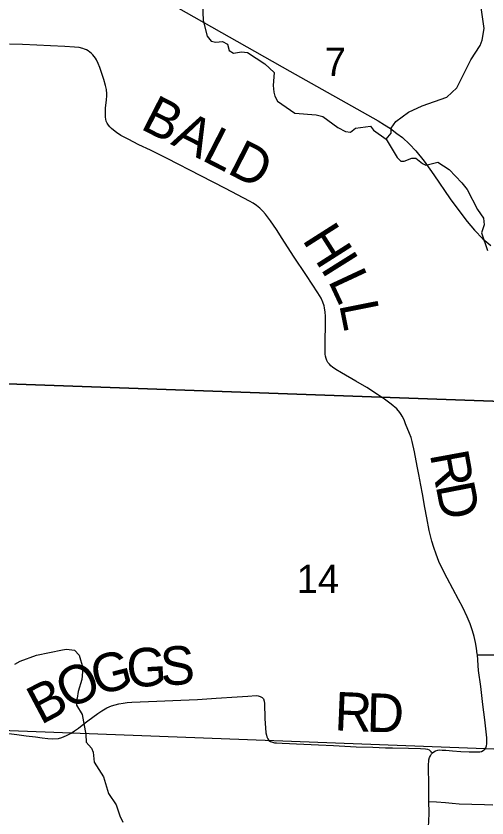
# Model space of a CAD drawing. Extents: x 0 to 34, y 0 to 22.
# Drawn here: x 6.614 to 7.308, y 17.641 to 18.823 of the extents above; entities that cross this region are included whole.
import ezdxf

# ---------------------------------------------------------------- set-up
doc = ezdxf.new("R2010")
doc.units = 0
for name, color, linetype in [('GM_X_County_Road', 7, 'Continuous'), ('GM_X_County_Road_Text', 7, 'Continuous'), ('GM_X_Minor_River', 7, 'Continuous'), ('GM_X_Rail_Line', 7, 'Continuous'), ('GM_X_Section', 7, 'Continuous'), ('GM_X_Section_Text', 7, 'Continuous'), ('GM_X_Township_Road', 7, 'Continuous'), ('GM_X_Township_Road_Text', 7, 'Continuous')]:
    doc.layers.add(name, color=color, linetype=linetype)

msp = doc.modelspace()

# ---------------------------------------------------------------- linework, layer by layer
at = {"layer": 'GM_X_County_Road'}
for points in [[(7.294, 17.8814), (7.2939, 17.8824), (7.2926, 17.8914), (7.2913, 17.8998), (7.2895, 17.9083), (7.2869, 17.917), (7.2834, 17.9272), (7.2792, 17.9373), (7.2724, 17.9511), (7.2663, 17.9631), (7.2579, 17.9787), (7.2493, 17.9945), (7.2435, 18.0058), (7.2374, 18.0189), (7.2331, 18.0298), (7.2297, 18.0395), (7.227, 18.0489), (7.2231, 18.0646), (7.2194, 18.0832), (7.2167, 18.0985), (7.213, 18.1188), (7.2105, 18.1317), (7.2078, 18.1474), (7.2055, 18.1596), (7.2013, 18.1809), (7.1979, 18.196), (7.1963, 18.2019), (7.1942, 18.2077), (7.1883, 18.2221), (7.186, 18.2278), (7.1833, 18.2332), (7.1817, 18.236), (7.1795, 18.239), (7.1754, 18.244), (7.167, 18.2511), (7.1571, 18.2584), (7.1469, 18.2654), (7.1311, 18.2754), (7.1151, 18.2849), (7.0936, 18.2973), (7.0856, 18.3021), (7.0804, 18.3057), (7.078, 18.3078), (7.0758, 18.3101), (7.0738, 18.3127), (7.0723, 18.3155), (7.0711, 18.3185), (7.0703, 18.3216), (7.0698, 18.3248), (7.0695, 18.3311), (7.0698, 18.3467), (7.0703, 18.3653), (7.0701, 18.3808), (7.0697, 18.3869), (7.0688, 18.393), (7.0682, 18.396), (7.0663, 18.4017), (7.0636, 18.4072), (7.0589, 18.4151), (7.0419, 18.441), (7.0232, 18.4695), (7.0065, 18.4956), (6.998, 18.5086), (6.9891, 18.5213), (6.9817, 18.5312), (6.9777, 18.5358), (6.9733, 18.5401), (6.9685, 18.5439), (6.9635, 18.5474), (6.9582, 18.5506), (6.9225, 18.5692), (6.8866, 18.5877), (6.8368, 18.6131), (6.812, 18.6256), (6.795, 18.6337), (6.7791, 18.6417), (6.7685, 18.6474), (6.7623, 18.6518), (6.7574, 18.6552), (6.7546, 18.6577), (6.7522, 18.66), (6.7503, 18.6623), (6.7485, 18.6654), (6.747, 18.6684), (6.7463, 18.6713), (6.7459, 18.6745), (6.7458, 18.6779), (6.7457, 18.6811), (6.746, 18.6874), (6.7474, 18.6997), (6.7478, 18.7059), (6.7477, 18.7089), (6.7471, 18.715), (6.7459, 18.721), (6.7432, 18.7298), (6.7373, 18.7474), (6.7351, 18.7532), (6.7325, 18.7587), (6.731, 18.7614), (6.7292, 18.7638), (6.7273, 18.7662), (6.7252, 18.7683), (6.7229, 18.7703), (6.7204, 18.7719), (6.7178, 18.7734), (6.7151, 18.7747), (6.7122, 18.7757), (6.7068, 18.777), (6.7004, 18.7777), (6.6859, 18.7786), (6.665, 18.7796), (6.6444, 18.7807), (6.6234, 18.7813), (6.6041, 18.7817)], [(7.2277, 17.7367), (7.2297, 17.7384), (7.2324, 17.7398), (7.2355, 17.7407), (7.2388, 17.7411), (7.242, 17.741), (7.2475, 17.7407), (7.2574, 17.7399), (7.2697, 17.739), (7.2821, 17.7386), (7.2945, 17.7382), (7.2974, 17.7383), (7.3003, 17.739), (7.3028, 17.7403), (7.305, 17.7421), (7.3066, 17.7444), (7.3076, 17.7471), (7.308, 17.7501), (7.3081, 17.7531), (7.3079, 17.7592), (7.3048, 17.7856), (7.3023, 17.8084), (7.2989, 17.8346), (7.2959, 17.8581), (7.294, 17.8814)], [(7.294, 17.8814), (7.3009, 17.8813), (7.3112, 17.8813), (7.3288, 17.8815), (7.3473, 17.8816), (7.3787, 17.8813), (7.4373, 17.8815), (7.456, 17.8815), (7.4621, 17.8811)], [(7.2227, 17.665), (7.2225, 17.6881), (7.2223, 17.698), (7.222, 17.7079), (7.2221, 17.7175), (7.2221, 17.7207), (7.2224, 17.7238), (7.2227, 17.7267), (7.2236, 17.7298), (7.2249, 17.7327), (7.2265, 17.7352), (7.2277, 17.7367)], [(7.1802, 17.3223), (7.1867, 17.3472), (7.1894, 17.3588), (7.1931, 17.3749), (7.1963, 17.3887), (7.1986, 17.3984), (7.2008, 17.4077), (7.2036, 17.4197), (7.206, 17.4299), (7.2083, 17.4409), (7.2096, 17.4482), (7.2111, 17.4564), (7.2119, 17.4638), (7.2134, 17.4847), (7.2144, 17.5034), (7.2154, 17.5259), (7.2173, 17.5649), (7.2198, 17.5933), (7.2216, 17.6233), (7.2223, 17.6353), (7.2228, 17.6488), (7.2227, 17.665)]]:
    msp.add_lwpolyline(points, dxfattribs=at)
at = {"layer": 'GM_X_Minor_River'}
for points in [[(7.1596, 18.6419), (7.1668, 18.6506), (7.1667, 18.6582), (7.1739, 18.6681), (7.1923, 18.6815), (7.2127, 18.6911), (7.249, 18.7038), (7.2637, 18.7176), (7.2846, 18.7587), (7.2982, 18.78), (7.3011, 18.7876), (7.3041, 18.8051), (7.2994, 18.8362), (7.2979, 18.8415), (7.297, 18.859), (7.3097, 18.8947)], [(6.8889, 18.8416), (6.8898, 18.8169), (6.8956, 18.7938), (6.9017, 18.7863), (6.9085, 18.7848), (6.9183, 18.786), (6.9259, 18.7818), (6.9279, 18.7727), (6.9343, 18.7686), (6.9464, 18.7705), (6.9551, 18.7695), (6.9809, 18.7529), (6.9946, 18.7404), (6.9932, 18.7211), (6.994, 18.7112), (6.9955, 18.7051), (6.9993, 18.698), (7.0248, 18.6802), (7.0562, 18.6778), (7.066, 18.6755), (7.0884, 18.6593), (7.0994, 18.6533), (7.107, 18.6522), (7.1142, 18.658), (7.1365, 18.6611), (7.141, 18.6551), (7.1596, 18.6419), (7.1757, 18.6146), (7.181, 18.6093), (7.1859, 18.6094), (7.1972, 18.6136), (7.2033, 18.614), (7.2131, 18.6061), (7.2181, 18.6035), (7.2355, 18.6081), (7.2522, 18.5972), (7.2712, 18.5776), (7.2788, 18.5674), (7.2944, 18.5382), (7.3032, 18.5253), (7.304, 18.5155), (7.2999, 18.5037), (7.3091, 18.4776)], [(6.6123, 17.8676), (6.6199, 17.8719), (6.644, 17.8807), (6.6826, 17.8889), (6.6886, 17.8897), (6.7, 17.8882), (6.7072, 17.8807), (6.7122, 17.8621), (6.7108, 17.845), (6.7056, 17.8271), (6.7041, 17.8177), (6.7026, 17.8127), (6.703, 17.807), (6.7114, 17.7934), (6.7169, 17.7638), (6.7173, 17.7528), (6.7253, 17.7437), (6.7276, 17.7377), (6.7292, 17.7233), (6.7429, 17.7017), (6.7502, 17.6771), (6.7616, 17.6604), (6.767, 17.6438), (6.7716, 17.6347)]]:
    msp.add_lwpolyline(points, dxfattribs=at)
at = {"layer": 'GM_X_Rail_Line'}
msp.add_lwpolyline([(6.8389, 18.8435), (7.0174, 18.7422), (7.1477, 18.6688), (7.1572, 18.6629), (7.1658, 18.6574), (7.1754, 18.6504), (7.1837, 18.6442), (7.1939, 18.6345), (7.2033, 18.6245), (7.2155, 18.6093), (7.2299, 18.5892), (7.254, 18.5541), (7.268, 18.5346), (7.2789, 18.5203), (7.2898, 18.5075), (7.3019, 18.4949), (7.3137, 18.4848)], dxfattribs=at)
at = {"layer": 'GM_X_Section'}
for points in [[(6.5918, 19.2905), (7.6132, 19.2594), (7.5782, 18.246), (6.5595, 18.2824)], [(6.5595, 18.2824), (7.5782, 18.246), (7.5651, 17.7332), (6.5395, 17.7719)]]:
    msp.add_lwpolyline(points, close=True, dxfattribs=at)
at = {"layer": 'GM_X_Township_Road'}
for points in [[(6.5953, 17.7663), (6.6151, 17.7638), (6.6289, 17.762), (6.6427, 17.7603), (6.6525, 17.7591), (6.6607, 17.7582), (6.6684, 17.7575), (6.6765, 17.7579), (6.6816, 17.7593), (6.6886, 17.7625), (6.6951, 17.7659), (6.7003, 17.7692), (6.7061, 17.7735), (6.7117, 17.7776), (6.72, 17.7841), (6.727, 17.7894), (6.7347, 17.795), (6.7405, 17.7988), (6.7477, 17.8033), (6.7545, 17.8062), (6.76, 17.8079), (6.7657, 17.8091), (6.772, 17.8103), (6.778, 17.811), (6.7845, 17.8115), (6.8217, 17.8132), (6.8568, 17.8144), (6.8813, 17.8156), (6.9092, 17.8173), (6.94, 17.8194), (6.9557, 17.8206), (6.9677, 17.8212), (6.9708, 17.8209), (6.9739, 17.82), (6.9766, 17.8183), (6.9787, 17.8163), (6.9799, 17.8132), (6.9802, 17.8096), (6.9807, 17.7877), (6.9823, 17.7666), (6.983, 17.7629), (6.9835, 17.7603), (6.9849, 17.7576), (6.9867, 17.7553), (6.9891, 17.7537), (6.9918, 17.7525), (6.9948, 17.7518), (6.9978, 17.7515), (7.0063, 17.7509), (7.0381, 17.7498), (7.0597, 17.7488), (7.0818, 17.7478), (7.1155, 17.7459), (7.14, 17.745), (7.1585, 17.7445), (7.1691, 17.7442), (7.1924, 17.7438), (7.2103, 17.7433), (7.2174, 17.7429), (7.2205, 17.7422), (7.2228, 17.7413), (7.2253, 17.7389), (7.2277, 17.7367)], [(7.2227, 17.665), (7.2337, 17.6646), (7.2472, 17.6637), (7.2569, 17.6627), (7.2672, 17.6619), (7.3045, 17.6606), (7.3167, 17.6603)]]:
    msp.add_lwpolyline(points, dxfattribs=at)

# ---------------------------------------------------------------- texts
at = {"layer": 'GM_X_County_Road_Text'}
for s, height, rotation, p in [('BALD', 0.05682, 332.8829, (6.7956, 18.658)), ('H', 0.0568, 302.4877, (7.0349, 18.4936)), ('I', 0.0568, 302.103, (7.0617, 18.4515)), ('L', 0.0568, 294.9799, (7.0733, 18.4334)), ('L', 0.0568, 281.2662, (7.0901, 18.3983)), ('R', 0.0568, 280.3998, (7.2238, 18.1776)), ('D', 0.0568, 281.0596, (7.2324, 18.131))]:
    msp.add_text(s, height=height, rotation=rotation, dxfattribs=at).set_placement(p)
at = {"layer": 'GM_X_Section_Text'}
for s, height, p in [('7', 0.0419, (7.0692, 18.7351)), ('14', 0.04186, (7.0279, 17.9724))]:
    msp.add_text(s, height=height, rotation=0, dxfattribs=at).set_placement(p)
at = {"layer": 'GM_X_Township_Road_Text'}
for s, rotation, p in [('G', 3.1707, (6.7782, 17.8333)), ('S', 2.9329, (6.828, 17.8361)), ('G', 14.417, (6.7327, 17.8213)), ('O', 27.6452, (6.6916, 17.7994)), ('B', 27.8725, (6.6504, 17.7776)), ('R', 357.5483, (7.0827, 17.7702)), ('D', 358.54, (7.1304, 17.7681))]:
    msp.add_text(s, height=0.0568, rotation=rotation, dxfattribs=at).set_placement(p)

doc.saveas('drawing.dxf')
